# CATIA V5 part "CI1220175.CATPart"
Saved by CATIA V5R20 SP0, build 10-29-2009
Part number: CI1220175
Bounding box of the stored display mesh (mm): x -19 to 19, y -22.289 to 21.949, z -205 to 15.368
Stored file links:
  C:\Users\Raffaele\Desktop\3D X SITO CF\BOLEX\19-INCLINED ASSEMBLY REF_CI\CI1220175.CATPart

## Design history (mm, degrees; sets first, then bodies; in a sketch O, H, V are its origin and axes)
Set1
  DatumSurface1 to DatumSurface16 "MANIFOLD_SOLID_BREP #389"
  DatumSurface17 "OPEN_SHELL #1184"
  DatumSurface18 "OPEN_SHELL #1184"
  DatumSurface19 "OPEN_SHELL #1251"
  DatumSurface20 "OPEN_SHELL #1251"
  DatumSurface21 to DatumSurface43 "MANIFOLD_SOLID_BREP #1252"
Body1 (main body)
